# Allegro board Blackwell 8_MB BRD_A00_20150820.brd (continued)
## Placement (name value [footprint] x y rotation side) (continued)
PG4602  GAP-CLOSE-PWR-3-GP  [GAP-CLOSE-PWR-3]  94.6 126.94 90 top
PG4603  GAP-CLOSE-PWR-3-GP  [GAP-CLOSE-PWR-3]  89.65 89.73 0 top
PG4604  GAP-CLOSE-PWR-3-GP  [GAP-CLOSE-PWR-3]  94.6 123.13 270 top
PG4605  GAP-CLOSE-PWR-3-GP  [GAP-CLOSE-PWR-3]  90.03 101.16 90 top
PKEY1  SW-TACT-5P-32-GP  [SKTDLDE010]  101.12 208.5 180 top
PL4601  IND-2D2UH-330-GP  [L6965-1330-UH60]  94.47 116.28 180 top
PL4701  IND-1UH-210-GP  [L2520-D620H48]  99.83 165.3 180 bottom
PL4702  IND-D47UH-78-GP  [L2016-D516H40]  96.18 165.58 180 bottom
PL4703  IND-D47UH-78-GP  [L2016-D516H40]  94.04 165.58 180 bottom
PL4704  IND-D47UH-78-GP  [L2016-D516H40]  91.91 167.25 180 bottom
PL4705  IND-D47UH-78-GP  [L2016-D516H40]  90.36 172.79 90 bottom
PL4706  IND-D47UH-78-GP  [L2016-D516H40]  92.62 179.57 90 bottom
PL4707  IND-D47UH-78-GP  [L2016-D516H40]  94.04 182.04 0 bottom
PL4708  IND-D47UH-78-GP  [L2016-D516H40]  90.54 174.9 90 bottom
PL4801  IND-1UH-210-GP  [L2520-D620H48]  109.31 180.51 270 bottom
PL4802  IND-D47UH-78-GP  [L2016-D516H40]  97.81 184.35 0 bottom
PL4803  IND-D47UH-78-GP  [L2016-D516H40]  105.95 178 270 bottom
PL4804  IND-D47UH-78-GP  [L2016-D516H40]  99.96 184.26 0 bottom
PL4805  IND-D47UH-78-GP  [L2016-D516H40]  102.07 184.26 0 bottom
PL4806  IND-D47UH-78-GP  [L2016-D516H40]  103.64 168.9 270 bottom
PL4807  IND-D47UH-78-GP  [L2016-D516H40]  105.85 173.12 180 bottom
PMIC1  BD2613GW-E2-3-GP  [BGA224J6D2H25]  99.43 175.33 90 bottom
PQ4601  2N7002KDW-GP  [SOT-363H44]  85.84 83.76 180 top
PQ4603  2N7002KDW-GP  [SOT-363H44]  98.41 83.99 180 top
PQ4901  SI2301CDS-T1-GE3-GP  [SOT23DGS2D4H45]  105.47 172.03 0 top
PR4601  22R1J-GP  [R0201H12]  95.49 93.16 180 top
PR4602  22R1J-GP  [R0201H12]  94.98 93.16 180 top
PR4603  10R5J-GP  [R805H24]  91.68 102.81 90 top
PR4605  20R3F-L-GP  [R603H22]  97.9 95.07 180 top
PR4606  1KR2F-3-GP  [R402H16]  98.67 125.04 270 top
PR4608  100KR2F-L1-GP  [R402H16]  91.17 95.07 90 top
PR4610  1KR2F-3-GP  [R402H16]  96.13 93.67 0 top
PR4613  8K2R3J-3-GP  [R603H22]  85.18 86.38 180 top
PR4614  0R2J-2-GP  [R402H16]  90.92 98.62 0 top
PR4615  8K2R3J-3-GP  [R603H22]  86.47 86.38 180 top
PR4617  0R3J-0-U-GP  [R603H22]  94.6 101.8 180 top
PR4618  D01R3721F-GP-U  [R3720H40]  86.8 90.24 180 top
PR4619  10KR2F-2-GP  [R402H16]  88 84.15 90 top
PR4620  100KR2J-1-GP  [R402H16]  88 83.38 90 top
PR4621  100KR2J-1-GP  [R402H16]  91.17 97.35 90 top
PR4622  D01R2512F-3-GP  [R2512H32]  94.6 125.04 180 top
PR4623  12K1R2F-L1-GP  [R402H16]  90.92 93.8 180 top
PR4624  100KR2F-L1-GP  [R402H16]  100.75 81.73 90 top
PR4625  100KR2J-1-GP  [R402H16]  96.89 93.67 0 top
PR4626  499KR2F-1-GP  [R402H16]  102.45 81.73 90 top
PR4627  0R2J-2-GP  [R402H16]  94.35 92.65 180 top
PR4628  100KR2J-1-GP  [R402H16]  96.89 100.53 90 top
PR4629  100KR2J-1-GP  [R402H16]  97.7 99.77 90 top
PR4630  100KR2F-L1-GP  [R402H16]  103.14 83.54 180 top
PR4631  182KR2F-GP  [R402H16]  101.26 84.88 90 top
PR4632  0R2J-2-GP  [R402H16]  93.03 91.97 270 top
PR4633  66K5R2F-GP  [R402H16]  91.68 93.8 180 top
PR4634  100KR2J-1-GP  [R402H16]  88 81.86 270 top
PR4635  0R2J-2-GP  [R402H16]  98.18 88.67 180 top
PR4636  100KR2J-1-GP  [R402H16]  89.78 81.61 90 top
PR4637  100KR2J-1-GP  [R402H16]  88 82.62 270 top
PR4640  10KR1J-GP  [R0201H12]  97.52 88.46 0 top
PR4642  10KR1J-GP  [R0201H12]  97.95 86.84 0 top
PR4643  10KR1J-GP  [R0201H12]  97.42 86.84 0 top
PR4645  10KR1J-GP  [R0201H12]  95.41 88.92 270 top
PR4646  10KR2F-2-GP  [R402H16]  104.02 82.32 180 top
PR4650  100KR2J-1-GP  [R402H16]  99.68 29.15 90 top
PR4901  D01R5F-GP  [R805H24]  106.54 164.41 270 top
PR4902  2R2F-GP  [R402H16]  106.79 160.6 0 top
PR4903  2R2F-GP  [R402H16]  106.79 162.38 180 top
PR4904  2R2F-GP  [R402H16]  107.43 165.81 90 top
PR4905  2R2F-GP  [R402H16]  105.65 165.81 270 top
PR4906  D005R6F-1-GP  [R1206H32]  108.32 161.49 180 top
PR4907  20KR2F-L-GP  [R402H16]  81.85 175.61 270 bottom
PR4908  20KR2F-L-GP  [R402H16]  81.85 176.37 270 bottom
PR4909  20KR2F-L-GP  [R402H16]  81.85 177.13 270 bottom
PR4911  1KR2J-1-GP  [R402H16]  101.59 162.38 0 top
PR4912  10KR2F-2-GP  [R402H16]  100.82 162.38 0 top
PR4913  0R0402-PAD-1-GP  [0R0402-PAD]  107.05 173.81 0 top
PR4914  10KR2F-2-GP  [R402H16]  103.11 162.38 0 top
PR5001  2K2R2F-GP  [R402H16]  100.82 170.25 0 top
PR5002  2K2R2F-GP  [R402H16]  100.06 170.25 0 top
PR5003  100KR2F-L1-GP  [R402H16]  100.06 181.02 0 top
PR5101  10KR2J-3-GP  [R402H16]  102.09 172.28 0 top
PR5102  24K9R2F-L-GP  [R402H16]  101.33 173.93 0 top
PR5103  24K9R2F-L-GP  [R402H16]  100.06 173.43 270 top
PR5104  24K9R2F-L-GP  [R402H16]  100.06 174.44 270 top
PR5105  0R0402-PAD-1-GP  [0R0402-PAD]  98.54 170.76 0 top
PR5106  10KR2J-3-GP  [R402H16]  100.42 95.47 0 bottom
PR5107  0R0402-PAD-1-GP  [0R0402-PAD]  105.9 181.94 90 bottom
PR5108  1KR1J-GP  [R0201H12]  105.65 185.29 90 bottom
PR5109  47KR2F-GP  [R402H16]  104 176.86 0 top
PR5110  0R0402-PAD-1-GP  [0R0402-PAD]  105.52 176.6 0 top
PR5111  0R0402-PAD-1-GP  [0R0402-PAD]  100.06 172.16 0 top
PR5112  0R0402-PAD-1-GP  [0R0402-PAD]  103.49 159.46 90 bottom
PR5113  1MR2F-GP  [R402H16]  100.19 179.14 180 top
PR5114  0R0402-PAD-1-GP  [0R0402-PAD]  105.65 153.87 0 bottom
PR5115  0R0402-PAD-1-GP  [0R0402-PAD]  98.23 177.87 0 top
PR5117  1KR2J-1-GP  [R402H16]  37.32 142.06 180 bottom
PU4601  BQ24770RUYR-3-GP  [QFN28-G2D7H32]  94.47 97.1 90 top
PU4602  SIS407DN-T1-GE3-1-GP  [PPAK-8P-2H45]  99.94 128.09 270 top
PU4603  FDMS3600-02-RJK0215-COLAY-GP  [PPAK-8P-G5324H44-COLAY]  93.84 109.29 270 top
PU4604  SI7121DN-T1-GE3-GP  [PPAK-8P-2H45]  90.03 86.43 270 top
Q501  2N7002W-7-GP  [SOT-323H44]  74.66 179.52 0 bottom
Q1701  PMBS3904-1-GP  [SOT-23-10H44]  89.01 112.85 270 top
Q1702  SI2301CDS-T1-GE3-GP  [SOT23DGS2D4H45]  87.31 28.9 90 bottom
Q1703  SI2301CDS-T1-GE3-GP  [SOT23DGS2D4H45]  91.05 127.58 270 top
Q3001  2N7002W-7-GP  [SOT-323H44]  96.07 68.75 180 top
Q4501  SIS407DN-T1-GE3-1-GP  [PPAK-8P-2H45]  100.57 124.28 0 bottom
R301  182R2F-GP  [R402H16]  69.46 163.77 0 top
R302  182R2F-GP  [R402H16]  69.33 162.38 270 top
R307  10KR1F-GP  [R0201H12]  69.71 178.3 0 bottom
R308  10KR1F-GP  [R0201H12]  69.2 178.3 0 bottom
R309  0R0201-PAD-GP  [0R0201-PAD]  54.98 167.71 180 bottom
R310  0R0201-PAD-GP  [0R0201-PAD]  54.22 180.41 180 bottom
R311  0R0201-PAD-GP  [0R0201-PAD]  53.58 160.98 0 bottom
R312  0R0201-PAD-GP  [0R0201-PAD]  55.1 147.77 180 bottom
R402  402R2F-GP  [R402H16]  82.18 174.32 180 bottom
R403  150R1F-GP  [R0201H12]  78.73 173.43 180 bottom
R404  150R1F-GP  [R0201H12]  78.22 173.43 0 bottom
R406  402R2F-GP  [R402H16]  83.53 172.28 180 bottom
R408  20KR2F-L-GP  [R402H16]  81.39 174.32 180 bottom
R410  10KR2J-3-GP  [R402H16]  78.98 177.74 180 bottom
R411  10KR2J-3-GP  [R402H16]  76.82 179.01 270 bottom
R412  10KR2J-3-GP  [R402H16]  78.6 179.01 90 bottom
R417  10KR2J-3-GP  [R402H16]  76.31 177.74 180 bottom
R418  10KR2J-3-GP  [R402H16]  75.55 177.74 180 bottom
R421  100KR1J-GP  [R0201H12]  89.24 54.38 0 bottom
R422  100KR1J-GP  [R0201H12]  88.99 53.61 90 bottom
R423  100KR1J-GP  [R0201H12]  90 54.02 270 bottom
R501  100R1F-GP  [R0201H12]  83.68 153.23 180 bottom
R502  402R2F-GP  [R402H16]  84.97 159.25 270 bottom
R503  0R2J-2-GP  [R402H16]  67.93 149.42 90 bottom
R504  80D6R1F-GP  [R0201H12]  77.28 158.85 90 top
R507  10KR1J-GP  [R0201H12]  77.2 148.28 270 bottom
R508  10KR1J-GP  [R0201H12]  74.15 152.6 0 bottom
R509  10KR1J-GP  [R0201H12]  70.67 151.07 0 bottom
R510  1KR1J-GP  [R0201H12]  78.35 151.33 180 bottom
R511  100KR1J-GP  [R0201H12]  71.18 151.07 0 bottom
R514  715R2F-GP  [R402H16]  73.77 177.24 90 bottom
R603  90D9R1F-GP  [R0201H11]  84.95 165.78 0 bottom
R604  100KR1J-GP  [R0201H12]  75.68 148.28 90 bottom
R624  2K2R1F-GP  [R0201H12]  70.09 149.42 180 bottom
R625  2K2R1F-GP  [R0201H12]  69.07 149.42 180 bottom
R626  2K2R1F-GP  [R0201H12]  73.01 152.85 270 bottom
R627  2K2R1F-GP  [R0201H12]  69.58 149.42 180 bottom
R628  2K2R1F-GP  [R0201H12]  70.6 149.42 180 bottom
R629  2K2R1F-GP  [R0201H12]  71.11 149.42 180 bottom
R630  2K2R1F-GP  [R0201H12]  73.01 151.33 270 bottom
R631  2K2R1F-GP  [R0201H12]  73.01 152.34 270 bottom
R632  2K2R1F-GP  [R0201H12]  73.01 150.82 270 bottom
R633  2K2R1F-GP  [R0201H12]  73.01 150.31 270 bottom
R634  2K2R1F-GP  [R0201H12]  73.01 151.84 270 bottom
R635  2K2R1F-GP  [R0201H12]  71.61 149.42 180 bottom
R636  2K2R1F-GP  [R0201H12]  73.01 149.8 270 bottom
R637  2K2R1F-GP  [R0201H12]  72.12 149.42 180 bottom
R640  45D3R2F-L-GP  [R402H16]  85.58 165.43 0 bottom
R643  113R2F-GP  [R402H16]  84.97 167.15 180 bottom
R644  100R1F-GP  [R0201H12]  76.69 151.33 0 bottom
R645  2K2R1F-GP  [R0201H12]  84.31 150.44 180 bottom
R647  2K2R1F-GP  [R0201H12]  84.82 150.44 180 bottom
R648  402R2F-GP  [R402H16]  85.58 163.65 0 bottom
R652  0R2J-2-GP  [R402H16]  76.69 149.93 0 bottom
R666  2K2R1F-GP  [R0201H12]  74.03 151.84 90 bottom
R667  2K2R1F-GP  [R0201H12]  74.03 151.33 90 bottom
R703  100KR1J-GP  [R0201H12]  70.22 176.35 0 bottom
R704  100KR1J-GP  [R0201H12]  84.19 153.23 180 bottom
R705  2K2R1F-GP  [R0201H12]  72.12 179.4 270 bottom
R707  10KR1J-GP  [R0201H12]  70.73 176.35 0 bottom
R711  10KR1J-GP  [R0201H12]  72.12 178.13 0 bottom
R713  10KR1J-GP  [R0201H12]  77.2 148.79 90 bottom
R714  100KR1J-GP  [R0201H12]  90.54 163.01 90 bottom
R715  2K49R2F-GP  [R402H16]  80.25 161.62 270 top
R716  200KR1J-GP  [R0201H12]  83.04 161.34 180 bottom
R719  10KR1J-GP  [R0201H12]  80.48 176.52 270 bottom
R720  10KR2J-3-GP  [R402H16]  71.23 177.24 90 bottom
R721  49D9R1F-GP  [R0201H12]  79.84 160.98 270 top
R722  0R2J-2-GP  [R402H16]  81.52 152.34 90 bottom
R723  0R2J-2-GP  [R402H16]  79.34 150.74 0 bottom
R724  2K2R1F-GP  [R0201H12]  72.12 178.89 270 bottom
R728  0R2J-2-GP  [R402H16]  81.14 150.82 0 bottom
R729  2K2R1F-GP  [R0201H12]  71.23 176.35 180 bottom
R730  10MR1J-GP  [R0201H12]  83.68 157.04 0 bottom
R731  10KR1J-GP  [R0201H12]  69.71 176.6 0 bottom
R732  10KR1J-GP  [R0201H12]  82.92 150.44 180 bottom
R733  10KR1J-GP  [R0201H12]  69.46 179.06 270 bottom
R734  10KR2J-3-GP  [R402H16]  77.51 176.14 90 bottom
R735  51R1F-GP  [R0201H12]  73.52 176.35 180 bottom
R736  51R1F-GP  [R0201H12]  72.12 179.9 270 bottom
R737  51R1F-GP  [R0201H12]  73.01 176.35 180 bottom
R738  51R1F-GP  [R0201H12]  72.38 176.35 180 bottom
R739  20KR1J-GP  [R0201H12]  80 159.2 90 top
R740  51R1F-GP  [R0201H12]  73.39 177.87 270 bottom
R741  10KR2J-3-GP  [R402H16]  75.83 176.14 270 bottom
R742  100KR1J-GP  [R0201H12]  74.26 147.34 270 bottom
R748  0R2J-2-GP  [R402H16]  68.57 178.38 0 bottom
R749  100R1F-GP  [R0201H12]  70.22 178.38 180 bottom
R750  0R2J-2-GP  [R402H16]  86.9 76.58 90 bottom
R751  51R1F-GP  [R0201H12]  73.39 178.38 270 bottom
R753  10KR1J-GP  [R0201H12]  71.61 178.13 180 bottom
R754  10KR1J-GP  [R0201H12]  71.74 176.35 180 bottom
R758  10KR1J-GP  [R0201H12]  72.63 178.13 180 bottom
R802  0R0402-PAD-1-GP  [0R0402-PAD]  83.04 163.77 180 bottom
R805  0R2J-2-GP  [R402H16]  80.25 166.06 90 top
R806  0R0402-PAD-1-GP  [0R0402-PAD]  80.25 166.82 270 top
R1305  240R1F-GP  [R0201H12]  48.12 173.43 90 bottom
R1306  240R1F-GP  [R0201H12]  48.12 172.92 90 bottom
R1307  240R1F-GP  [R0201H12]  52.44 180.41 0 bottom
R1308  240R1F-GP  [R0201H12]  51.93 180.41 0 bottom
R1309  40D2R1F-GP  [R0201H12]  54.86 174.42 90 top
R1310  40D2R1F-GP  [R0201H12]  54.72 175.2 0 top
R1311  40D2R1F-GP  [R0201H12]  55.23 175.2 0 top
R1312  40D2R1F-GP  [R0201H12]  56.63 174.06 180 top
R1313  40D2R1F-GP  [R0201H12]  54.09 175.46 180 top
R1314  40D2R1F-GP  [R0201H12]  54.44 173.63 270 top
R1315  40D2R1F-GP  [R0201H12]  53.4 173.22 270 top
R1316  40D2R1F-GP  [R0201H12]  52.87 173.83 270 top
R1317  40D2R1F-GP  [R0201H12]  52.83 174.38 270 top
R1318  40D2R1F-GP  [R0201H12]  52.56 175.03 270 top
R1322  300R1J-GP  [R0201H12]  51.42 174.57 90 top
R1323  300R1J-GP  [R0201H12]  54.22 177.36 180 top
R1324  10KR1J-GP  [R0201H12]  54.98 180.16 90 bottom
R1325  10KR1J-GP  [R0201H12]  54.98 180.67 270 bottom
R1326  10KR1J-GP  [R0201H12]  53.96 167.71 0 bottom
R1327  10KR1J-GP  [R0201H12]  54.47 167.71 180 bottom
R1405  240R1F-GP  [R0201H12]  55.61 147.77 180 bottom
R1406  240R1F-GP  [R0201H12]  56.12 147.77 180 bottom
R1407  240R1F-GP  [R0201H12]  48.12 151.96 90 bottom
R1408  240R1F-GP  [R0201H12]  48.14 151.42 90 bottom
R1409  40D2R1F-GP  [R0201H12]  53.96 154.25 0 top
R1410  40D2R1F-GP  [R0201H12]  52.82 153.87 90 top
R1411  40D2R1F-GP  [R0201H12]  52.82 154.38 90 top
R1412  40D2R1F-GP  [R0201H12]  54.22 153.23 180 top
R1413  40D2R1F-GP  [R0201H12]  53.71 153.23 180 top
R1414  40D2R1F-GP  [R0201H12]  56.22 154.88 270 top
R1415  40D2R1F-GP  [R0201H12]  56.22 154.38 270 top
R1416  40D2R1F-GP  [R0201H12]  55.74 152.73 0 top
R1417  40D2R1F-GP  [R0201H12]  54.72 153.23 180 top
R1418  40D2R1F-GP  [R0201H12]  55.23 153.23 180 top
R1422  300R1J-GP  [R0201H12]  54.22 148.66 90 top
R1423  300R1J-GP  [R0201H12]  51.29 153.87 270 top
R1424  10KR1J-GP  [R0201H12]  54.34 148.03 270 bottom
R1425  10KR1J-GP  [R0201H12]  54.34 147.52 90 bottom
R1426  10KR1J-GP  [R0201H12]  54.34 160.73 90 bottom
R1427  10KR1J-GP  [R0201H12]  54.34 161.23 270 bottom
R1502  0R5J-5-GP  [R805H24]  61.96 149.04 90 bottom
R1601  0R0402-PAD-1-GP  [0R0402-PAD]  103.9 155.62 90 bottom
R1602  0R0402-PAD-1-GP  [0R0402-PAD]  95.36 161.03 90 bottom
R1701  49D9R1F-GP  [R0201H12]  87.92 20.52 270 top
R1702  10KR1J-GP  [R0201H12]  89.9 27.76 0 top
R1705  10KR1J-GP  [R0201H12]  90.44 34.87 270 bottom
R1706  10KR1J-GP  [R0201H12]  90.44 35.38 270 bottom
R1707  10KR1J-GP  [R0201H12]  104.2 39.16 90 top
R1708  100KR1J-GP  [R0201H12]  99.17 31.57 90 top
R1709  10KR1J-GP  [R0201H12]  99.94 26.23 270 top
R1710  10KR1J-GP  [R0201H12]  104.96 39.42 180 top
R1711  1KR1J-GP  [R0201H12]  87.84 49.07 270 top
R1712  1KR1J-GP  [R0201H12]  88.17 47.19 180 top
R1713  100KR1J-GP  [R0201H12]  91.98 27.27 180 top
R1714  1KR1J-GP  [R0201H12]  87.67 47.19 180 top
R1715  1KR1J-GP  [R0201H12]  92.44 24.96 180 top
R1716  10KR1J-GP  [R0201H12]  94.09 40.58 180 top
R1717  10KR1J-GP  [R0201H12]  92.01 35.15 270 bottom
R1718  10KR1J-GP  [R0201H12]  89.01 36.52 0 bottom
R1719  100KR1J-GP  [R0201H12]  89.14 128.19 0 top
R1720  10KR1J-GP  [R0201H12]  86.45 40.61 0 top
R1721  0R0402-PAD-1-GP  [0R0402-PAD]  85.23 29.69 180 bottom
R1722  10KR1J-GP  [R0201H12]  100.32 35.38 0 top
R1723  10KR1J-GP  [R0201H12]  85.46 32.96 270 bottom
R1724  10KR1J-GP  [R0201H12]  85.84 35.63 270 top
R1725  10KR1J-GP  [R0201H12]  89.62 33.75 180 bottom
R1726  10KR1J-GP  [R0201H12]  87.92 19.98 90 top
R1727  10KR1J-GP  [R0201H12]  89.78 23.57 270 top
R1728  10KR1J-GP  [R0201H12]  99.05 38.68 90 top
R1729  10KR1J-GP  [R0201H12]  93.46 40.58 0 top
R1730  100KR1J-GP  [R0201H12]  100.32 37.43 180 top
R1731  0R2J-2-GP  [R402H16]  98.03 40.46 90 top
R1732  100KR1J-GP  [R0201H12]  100.32 36.42 180 top
R1733  10KR1J-GP  [R0201H12]  87.92 16.38 90 top
R1734  10KR1J-GP  [R0201H12]  86.98 40.61 0 top
R1735  10KR1J-GP  [R0201H12]  87.92 19.48 90 top
R1736  100KR1J-GP  [R0201H12]  88.17 46.17 180 top
R1737  0R2J-2-GP  [R402H16]  96.25 40.46 90 top
R1738  1MR2F-GP  [R402H16]  85.58 30.93 270 top
R1739  0R1J-GP  [R0201H12]  100.06 32.2 180 top
R1740  100KR1J-GP  [R0201H12]  87.26 23.36 0 bottom
R1741  100KR1J-GP  [R0201H12]  87.26 24.38 0 bottom
R1742  10KR1J-GP  [R0201H12]  85.08 28.27 180 bottom
R1743  1MR2F-GP  [R402H16]  85.13 29.71 0 top
R1744  10KR1J-GP  [R0201H12]  92.95 40.58 0 top
R1745  100KR1J-GP  [R0201H12]  100.44 34.36 0 top
R1746  1MR2F-GP  [R402H16]  99.22 36.8 90 top
R1747  100KR1J-GP  [R0201H12]  100.44 33.35 0 top
R1748  1MR2F-GP  [R402H16]  101.33 40.46 90 top
R1749  100KR2J-1-GP  [R402H16]  89.52 24.71 180 top
R1750  200KR2J-L1-GP  [R402H16]  90.28 24.71 0 top
R1752  100KR1J-GP  [R0201H12]  87.67 46.17 180 top
R1754  953R2F-GP  [R402H16]  89.27 40.58 270 top
R1757  0R2J-2-GP  [R402H16]  96.76 25.34 270 top
R1758  1KR1J-GP  [R0201H12]  87.87 40.58 90 top
R1759  8K2R2J-3-GP  [R402H16]  92.06 29.54 0 bottom
R1760  1KR1J-GP  [R0201H12]  98.54 29.28 180 top
R1761  100KR1J-GP  [R0201H12]  93.59 27.76 180 top
R1763  10KR1J-GP  [R0201H12]  87.92 18.97 90 top
R1764  10KR1J-GP  [R0201H12]  87.92 18.46 90 top
R1765  10KR1J-GP  [R0201H12]  87.92 17.95 90 top
R1767  10KR1J-GP  [R0201H12]  87.92 16.91 90 top
R1769  100KR1J-GP  [R0201H12]  85.84 38.68 270 top
R1770  10KR1J-GP  [R0201H12]  87.92 17.44 90 top
R1775  10KR1J-GP  [R0201H12]  99.17 32.08 270 top
R1776  10KR1J-GP  [R0201H12]  99.17 32.58 270 top
R1777  10KR1J-GP  [R0201H12]  99.17 33.09 270 top
R1778  10KR1J-GP  [R0201H12]  99.17 34.11 270 top
R1779  10KR1J-GP  [R0201H12]  99.17 33.6 270 top
R1780  10KR1J-GP  [R0201H12]  99.94 34.16 180 top
R1781  10KR1J-GP  [R0201H12]  92.57 27.76 180 top
R1782  10KR1J-GP  [R0201H12]  89.39 27.76 180 top
R1783  10KR1J-GP  [R0201H12]  90.41 27.76 180 top
R1784  10KR1J-GP  [R0201H12]  90.03 31.19 90 bottom
R1785  10KR1J-GP  [R0201H12]  92.82 26.97 90 top
R1786  10KR1J-GP  [R0201H12]  103.95 40.46 180 top
R1787  10KR1J-GP  [R0201H12]  103.41 40.46 0 top
R1788  10KR1J-GP  [R0201H12]  103.41 39.42 0 top
R1789  10KR1J-GP  [R0201H12]  104.2 39.67 270 top
R1801  0R0201-PAD-GP  [0R0201-PAD]  37.4 159.13 0 bottom
R1802  0R0201-PAD-GP  [0R0201-PAD]  38.67 167.25 180 bottom
R1803  3K3R1J-GP  [R0201H12]  37.91 159.13 0 bottom
R1804  10KR1J-GP  [R0201H12]  40.17 159.41 270 bottom
R1805  3K3R1J-GP  [R0201H12]  39.18 167.25 180 bottom
R2001  0R0402-PAD-1-GP  [0R0402-PAD]  104.76 193.11 90 bottom
R2002  100KR1J-GP  [R0201H12]  100.06 204.03 180 bottom
R2005  0R0402-PAD-1-GP  [0R0402-PAD]  96.02 195.96 180 bottom
R2012  22R2F-1-GP  [R402H16]  102.98 205.56 0 bottom
R2013  22R2F-1-GP  [R402H16]  100.19 205.56 0 bottom
R2014  0R0402-PAD-1-GP  [0R0402-PAD]  100.7 203.78 180 bottom
R2015  0R0402-PAD-1-GP  [0R0402-PAD]  96 194.13 0 bottom
R2016  0R0402-PAD-1-GP  [0R0402-PAD]  93.84 194.89 0 bottom
R2017  0R0402-PAD-1-GP  [0R0402-PAD]  89.14 193.62 0 bottom
R2018  0R0201-PAD-GP  [0R0201-PAD]  95.24 196.29 180 bottom
R2019  0R0201-PAD-GP  [0R0201-PAD]  96.76 195.12 180 bottom
R2020  0R0201-PAD-GP  [0R0201-PAD]  104.63 203.98 0 bottom
R2021  0R1J-GP  [R0201H12]  99.05 205.18 270 bottom
R2022  0R0402-PAD-1-GP  [0R0402-PAD]  106.67 194.38 180 bottom
R2023  20KR2J-L2-GP  [R402H16]  99.94 193.62 0 bottom
R2024  0R0402-PAD-1-GP  [0R0402-PAD]  105.78 194.38 180 bottom
R2025  0R0402-PAD-1-GP  [0R0402-PAD]  104.25 194.38 180 bottom
R2026  0R0402-PAD-1-GP  [0R0402-PAD]  105.02 194.38 180 bottom
R2027  0R0402-PAD-1-GP  [0R0402-PAD]  101.71 193.49 0 bottom
R2104  0R0201-PAD-GP  [0R0201-PAD]  111.62 146.88 180 top
R2107  0R0603-PAD-2-GP-U  [0R0603-PAD-1-U]  90.79 22.68 180 bottom
R2108  0R0603-PAD-2-GP-U  [0R0603-PAD-1-U]  89.52 22.68 180 bottom
R2201  2K2R1F-GP  [R0201H12]  97.8 200.78 0 bottom
R2202  2K2R1F-GP  [R0201H12]  95.87 204.03 0 bottom
R2203  0R0201-PAD-GP  [0R0201-PAD]  87.87 195.47 90 bottom
R2204  0R0402-PAD-1-GP  [0R0402-PAD]  87.29 195.42 90 top
R2205  0R0402-PAD-1-GP  [0R0402-PAD]  97.01 206.57 90 bottom
R2206  0R0402-PAD-1-GP  [0R0402-PAD]  105.5 199.13 0 bottom
R2207  0R0201-PAD-GP  [0R0201-PAD]  86.6 195.52 90 bottom
R2208  0R0201-PAD-GP  [0R0201-PAD]  95.87 205.18 0 bottom
R2209  33R2J-2-GP  [R402H16]  94.86 198.95 90 bottom
R2210  33R2J-2-GP  [R402H16]  94.27 203.75 90 bottom
R2211  0R2J-2-GP  [R402H16]  95.24 205.05 180 bottom
R2301  0R0201-PAD-GP  [0R0201-PAD]  107.3 104.59 270 bottom
R2302  0R0201-PAD-GP  [0R0201-PAD]  107.3 103.2 270 bottom
R2303  0R0201-PAD-GP  [0R0201-PAD]  106.41 111.45 270 bottom
R2304  0R0201-PAD-GP  [0R0201-PAD]  106.41 110.05 270 bottom
R2305  0R0201-PAD-GP  [0R0201-PAD]  107.3 105.86 270 bottom
R2306  0R0201-PAD-GP  [0R0201-PAD]  106.41 108.66 270 bottom
R2401  0R0201-PAD-GP  [0R0201-PAD]  113.19 100.15 180 bottom
R2403  0R0201-PAD-GP  [0R0201-PAD]  112.41 93.92 180 bottom
R2501  1KR2J-1-GP  [R402H16]  111.62 196.87 270 top
R2502  0R0201-PAD-GP  [0R0201-PAD]  109.43 193.21 0 top
R2503  0R0201-PAD-GP  [0R0201-PAD]  94.65 189.91 180 top
R2504  100KR1J-GP  [R0201H12]  95.16 189.05 0 top
R2505  0R0201-PAD-GP  [0R0201-PAD]  72.56 183.12 0 bottom
R2506  0R0201-PAD-GP  [0R0201-PAD]  72.05 183.12 0 bottom
R2508  0R0201-PAD-GP  [0R0201-PAD]  107.76 194.41 180 top
R2509  0R0201-PAD-GP  [0R0201-PAD]  66.92 183.84 270 bottom
R2510  0R0201-PAD-GP  [0R0201-PAD]  79.51 187.27 180 bottom
R2511  0R0201-PAD-GP  [0R0201-PAD]  106.79 191.71 180 top
R2512  0R0201-PAD-GP  [0R0201-PAD]  76.47 185.08 0 bottom
R2513  0R0201-PAD-GP  [0R0201-PAD]  107.05 188.41 270 top
R2514  0R0402-PAD-1-GP  [0R0402-PAD]  74.54 186.02 0 bottom
R2515  0R0402-PAD-1-GP  [0R0402-PAD]  89.95 187.55 90 top
R2517  0R1J-GP  [R0201H12]  78.47 187.4 90 bottom
R2518  0R1J-GP  [R0201H12]  73.39 184.14 90 bottom
R2903  15KR2F-GP  [R402H16]  104 19.88 270 top
R2905  93K1R2F-L-GP  [R402H16]  103.87 20.65 270 top
R2908  0R2J-2-GP  [R402H16]  103.87 22.17 270 top
R2909  0R2J-2-GP  [R402H16]  103.87 22.93 270 top
R2910  0R2J-2-GP  [R402H16]  103.87 23.69 270 top
R2911  0R2J-2-GP  [R402H16]  103.62 26.23 270 top
R2912  3K3R1J-GP  [R0201H12]  109.33 28.27 180 top
R2913  3K3R1J-GP  [R0201H12]  106.41 35.38 90 top
R2914  3K3R1J-GP  [R0201H12]  107.45 36.67 180 top
R2915  3K3R1J-GP  [R0201H12]  107.96 36.67 180 top
R2916  0R2J-2-GP  [R402H16]  107.63 25.65 180 top
R2917  0R2J-2-GP  [R402H16]  106.87 25.65 180 top
R2918  1KR2J-1-GP  [R402H16]  104.89 46.07 90 top
R2919  0R0402-PAD-1-GP  [0R0402-PAD]  101.74 18.23 180 top
R2920  0R0402-PAD-1-GP  [0R0402-PAD]  102.53 18.23 180 top
R2921  0R2J-2-GP  [R402H16]  95.41 22.52 270 top
R2922  0R2J-2-GP  [R402H16]  96.94 64.18 180 top
R2923  0R0402-PAD-1-GP  [0R0402-PAD]  103.62 142.57 180 top
R2924  0R0402-PAD-1-GP  [0R0402-PAD]  99.02 25.5 90 top
R2925  0R2J-2-GP  [R402H16]  99.05 24.58 270 top
R3001  100KR1J-GP  [R0201H12]  97.7 70.18 0 top
R3002  1MR2F-GP  [R402H16]  97.73 68.8 0 top
R3016  4K7R1J-GP  [R0201H12]  98.08 73.32 90 top
R3017  4K7R1J-GP  [R0201H12]  98.08 72.82 270 top
R3019  0R0402-PAD-1-GP  [0R0402-PAD]  97.42 66.34 90 top
R3020  0R2J-2-GP  [R402H16]  97.42 67.2 90 top
R3021  100KR1J-GP  [R0201H12]  107.78 70.1 270 top
R3022  100KR1J-GP  [R0201H12]  107.78 69.59 270 top
R3026  10KR1J-GP  [R0201H12]  98.67 67.94 180 top
R3101  0R0402-PAD-1-GP  [0R0402-PAD]  97.73 64.18 0 top
R3125  0R0201-PAD-GP  [0R0201-PAD]  102.4 59.05 0 top
R3126  0R0201-PAD-GP  [0R0201-PAD]  102.91 59.05 0 top
R3127  0R0201-PAD-GP  [0R0201-PAD]  103.41 59.05 0 top
R3128  0R0201-PAD-GP  [0R0201-PAD]  103.92 59.05 0 top
R3129  0R0201-PAD-GP  [0R0201-PAD]  101.21 86.81 270 bottom
R3130  0R0201-PAD-GP  [0R0201-PAD]  104.43 59.05 180 top
R3131  0R0201-PAD-GP  [0R0201-PAD]  101.89 59.05 180 top
R3146  0R0402-PAD-1-GP  [0R0402-PAD]  107.94 87.57 90 bottom
R3161  4K7R1J-GP  [R0201H12]  100.95 83.51 0 bottom
R3162  0R1J-GP  [R0201H12]  101.46 83.51 180 bottom
R3163  4K7R1J-GP  [R0201H12]  108.19 83.64 90 bottom
R3164  0R1J-GP  [R0201H12]  107.43 83.38 180 bottom
R3165  0R0201-PAD-GP  [0R0201-PAD]  101.21 86.3 270 bottom
R3166  0R1J-GP  [R0201H12]  101.46 85.54 180 bottom
R3167  4K7R1J-GP  [R0201H12]  100.95 85.54 0 bottom
R3168  4K7R1J-GP  [R0201H12]  108.19 85.16 90 bottom
R3169  0R1J-GP  [R0201H12]  107.43 85.42 0 bottom
R3170  4K7R1J-GP  [R0201H12]  108.19 84.65 90 bottom
R3171  4K7R1J-GP  [R0201H12]  100.95 84.53 0 bottom
R3172  0R1J-GP  [R0201H12]  101.46 84.53 180 bottom
R3173  0R1J-GP  [R0201H12]  107.43 84.4 180 bottom
R3401  100KR1J-GP  [R0201H12]  94.45 57.07 0 top
R3402  100KR1J-GP  [R0201H12]  93.15 58.87 270 top
R3403  100KR2J-1-GP  [R402H16]  88.86 49.32 0 top
R3404  100KR1J-GP  [R0201H12]  85.58 54.86 180 bottom
R3405  0R2J-2-GP  [R402H16]  92.14 37.16 90 bottom
R3407  1KR2J-1-GP  [R402H16]  88.4 51.05 180 top
R3408  1KR2J-1-GP  [R402H16]  87.64 51.05 180 top
R3807  10KR1J-GP  [R0201H12]  112.6 133.9 0 top
R3902  0R0402-PAD-1-GP  [0R0402-PAD]  98.03 77.16 180 top
R3904  0R0402-PAD-1-GP  [0R0402-PAD]  91.93 75.89 90 bottom
R3905  0R2J-2-GP  [R402H16]  94.22 78.3 270 top
R4003  100KR1J-GP  [R0201H12]  9.38 141.8 180 bottom
R4004  0R1J-GP  [R0201H12]  14.34 141.55 180 bottom
R4005  10KR1J-GP  [R0201H12]  13.32 140.53 0 bottom
R4006  0R1J-GP  [R0201H12]  18.02 141.55 180 bottom
R4007  0R1J-GP  [R0201H12]  18.53 141.55 180 bottom
R4008  0R1J-GP  [R0201H12]  13.32 141.55 0 bottom
R4009  0R1J-GP  [R0201H12]  17.51 141.55 180 bottom
R4010  0R1J-GP  [R0201H12]  69.1 176.55 180 bottom
R4012  0R1J-GP  [R0201H12]  23.86 141.68 180 bottom
R4013  0R1J-GP  [R0201H12]  21.07 142.06 0 bottom
R4014  0R1J-GP  [R0201H12]  20.56 142.06 0 bottom
R4017  100KR2J-1-GP  [R402H16]  11.92 141.55 90 bottom
R4018  10KR1J-GP  [R0201H12]  9.89 141.8 180 bottom
R4020  100KR2J-1-GP  [R402H16]  11.04 142.31 90 bottom
R4021  0R1J-GP  [R0201H12]  13.83 141.55 180 bottom
R4101  10KR1J-GP  [R0201H12]  82.74 184.2 0 bottom
R4102  0R0402-PAD-1-GP  [0R0402-PAD]  86.09 187.02 180 bottom
R4103  0R0201-PAD-GP  [0R0201-PAD]  80.38 186.61 90 bottom
R4104  1KR2J-1-GP  [R402H16]  84.64 183.97 0 bottom
R4105  0R0402-PAD-1-GP  [0R0402-PAD]  84.82 189.53 180 bottom
R4106  10KR1J-GP  [R0201H12]  80.5 185.14 0 bottom
R4107  0R0201-PAD-GP  [0R0201-PAD]  80.38 187.12 90 bottom
R4108  0R0201-PAD-GP  [0R0201-PAD]  82.23 184.2 0 bottom
R4109  0R0201-PAD-GP  [0R0201-PAD]  81.72 184.2 180 bottom
R4110  0R0201-PAD-GP  [0R0201-PAD]  81.22 184.2 180 bottom
R4201  0R0402-PAD-1-GP  [0R0402-PAD]  41.46 176.73 270 top
R4202  0R0402-PAD-1-GP  [0R0402-PAD]  42.15 174.59 270 top
R4203  0R0402-PAD-1-GP  [0R0402-PAD]  35.93 177.74 180 top
R4204  0R0402-PAD-1-GP  [0R0402-PAD]  39.74 177.87 180 top
R4205  0R0402-PAD-1-GP  [0R0402-PAD]  113.23 134.28 180 top
R4207  0R0402-PAD-1-GP  [0R0402-PAD]  38.44 176.02 0 top
R4208  0R0402-PAD-1-GP  [0R0402-PAD]  39.2 175.53 0 top
R4209  10KR1J-GP  [R0201H12]  40.04 176.14 180 top
R4301  0R0402-PAD-1-GP  [0R0402-PAD]  94.98 73.86 180 top
R4302  0R2J-2-GP  [R402H16]  94.09 73.86 180 top
R4303  1KR1J-GP  [R0201H12]  87.84 49.58 90 top
R4310  100KR1J-GP  [R0201H12]  87.74 74.49 180 bottom
R4311  100KR1J-GP  [R0201H12]  93.84 75.76 180 bottom
R4401  63K4R2F-2-GP  [R402H16]  101.18 49.25 270 top
R4402  30KR2F-GP  [R402H16]  103.19 49.75 270 top
R4403  100KR1J-GP  [R0201H12]  102.83 55.27 270 top
R4404  2KR2J-1-GP  [R402H16]  107.81 52.52 90 top
R4405  2KR2J-1-GP  [R402H16]  95.87 59.63 270 top
R4501  200KR2J-L1-GP  [R402H16]  101.46 127.58 270 bottom
R4502  100R2J-2-GP  [R402H14]  88.12 129.99 90 top
R4503  100R2J-2-GP  [R402H14]  88.12 130.75 90 top
R4504  100R2J-2-GP  [R402H14]  88.12 133.42 90 top
R4801  0R3J-6-GP  [R603H22]  108.8 183.81 0 bottom
R4902  300R1J-GP  [R0201H12]  100.85 16.02 270 bottom
R4903  1KR1J-GP  [R0201H12]  100.85 15.46 270 bottom
R5211  10KR2J-3-GP  [R402H16]  91.68 143.2 180 top
R5212  255KR1F-GP  [R0201H12]  92.7 143.45 90 top
R5213  300KR1F-GP  [R0201H12]  92.7 142.95 90 top
R5214  0R0201-PAD-GP  [0R0201-PAD]  91.3 144.72 270 top
R5215  100KR1F-GP  [R0201H12]  93.46 143.2 0 top
R5216  1KR1F-GP  [R0201H12]  93.97 142.18 0 top
R5217  0R2J-2-GP  [R402H16]  89.14 143.58 0 top
R5218  91KR1F-GP  [R0201H11]  94.22 142.95 90 top
R5219  28KR1F-GP  [R0201H12]  94.22 143.45 270 top
R5401  10KR1J-GP  [R0201H12]  113.14 196.26 90 top
R5403  100R1J-GP  [R0201H12]  105.52 195.91 180 top
R5404  100R1J-GP  [R0201H12]  114.03 178 270 top
R5405  100R1J-GP  [R0201H12]  113.27 150.08 180 top
R5406  100R1J-GP  [R0201H12]  111.77 192.35 0 top
R5409  10KR1J-GP  [R0201H12]  101.84 130.5 90 bottom
R5410  100KR2J-1-GP  [R402H16]  103.24 130.5 90 bottom
R5412  100R1J-GP  [R0201H12]  102.98 131.9 90 top
R5601  0R0402-PAD-1-GP  [0R0402-PAD]  63.87 142.95 270 bottom
R5602  0R0402-PAD-1-GP  [0R0402-PAD]  63.87 143.71 270 bottom
R5603  0R2J-2-GP  [R402H16]  48.12 140.28 90 bottom
R5704  0R0402-PAD-1-GP  [0R0402-PAD]  42.02 154.12 0 bottom
R5705  0R2J-2-GP  [R402H16]  41.95 156.38 0 bottom
R5706  0R0402-PAD-1-GP  [0R0402-PAD]  40.5 158.44 90 bottom
R5707  0R0402-PAD-1-GP  [0R0402-PAD]  39.61 157.55 270 bottom
R5712  0R0402-PAD-1-GP  [0R0402-PAD]  39.23 149.17 0 bottom
R5717  100KR1J-GP  [R0201H12]  41.52 150.06 90 bottom
R5720  100KR1J-GP  [R0201H12]  40.5 150.06 90 bottom
R5721  294KR2F-1-GP  [R402H16]  104.02 84.09 180 top
R5722  340KR2F-L-GP  [R402H16]  105.68 84.6 90 top
R5723  1KR1J-GP  [R0201H12]  98.16 85.92 270 top
R5724  1KR1J-GP  [R0201H12]  96.63 83.76 0 top
R5725  100KR1J-GP  [R0201H12]  42.02 146.76 90 bottom
R5726  100KR1J-GP  [R0201H12]  41.01 146.76 90 bottom
RAM1  H9CCNNNBKTMLBR-NTD-GP  [BGA253G110115H38]  54.72 174.06 270 bottom
RAM2  H9CCNNNBKTMLBR-NTD-GP  [BGA253G110115H38]  54.47 154.38 0 bottom
RT5101  NTC-47K-6-GP-U  [NTC-402H22-U]  92.06 161.49 0 bottom
RT5102  NTC-47K-6-GP-U  [NTC-402H22-U]  104.23 55.27 90 top
RT5103  NTC-47K-6-GP-U  [NTC-402H22-U]  51.57 164.21 0 bottom
RTC1  ACES-CON2-15-GP-U1  [50281-0020N-001]  33.02 137.76 180 bottom
SH1  MB_EMI_SHIELDING_FRAME_ SOC_T4  [SKT1603X1424-24]  66.72 164.07 180 bottom
SH2  SKT951X1419-24-S-GP  [SKT951X1419-24-S]  97.6 62.27 0 top
SH4  SKT520X1447-24-GP  [SKT520X1447-24]  104.92 98.07 180 bottom
SH5  SKT560X460-24-GP  [SKT560X460-24]  102.34 15.49 180 bottom
SPK1  ACES-CON2-15-GP-U1  [50281-0020N-001]  87.02 16.94 90 bottom
SPR1  SPRING-171-GP  [SPR5128H111]  82.52 191.1 270 bottom
SPR2  SPRING-171-GP  [SPR5128H111]  55.02 165.1 180 top
SPR3  SPRING-171-GP  [SPR5128H111]  80.02 139.1 270 top
SPR4  SPRING-123-GP  [SPR4013-1H75]  93.05 16.07 90 top
TP1  ACES-CON10-57-GP  [51651-01001-001]  94.02 71.55 180 bottom
TP401  TPAD14-OP-GP  [TPAD14-OP]  77.99 174.67 180 bottom
TP601  TPAD14-OP-GP  [TPAD14-OP]  83.55 149.4 180 bottom
TP701  TPAD14-OP-GP  [TPAD14-OP]  89.5 153.06 180 bottom
TP702  TPAD14-OP-GP  [TPAD14-OP]  76.62 152.52 180 bottom
TP801  TPAD14-OP-GP  [TPAD14-OP]  71.89 152.39 180 bottom
TP802  TPAD14-OP-GP  [TPAD14-OP]  70.95 163.7 0 top
TP803  TPAD14-OP-GP  [TPAD14-OP]  80.2 173.93 180 bottom
TP804  TPAD14-OP-GP  [TPAD14-OP]  76.19 163.52 0 top
TP805  TPAD14-OP-GP  [TPAD14-OP]  70.98 179.24 180 bottom
TP1601  TPAD14-OP-GP  [TPAD14-OP]  78.09 149.83 90 bottom
TP1602  TPAD14-OP-GP  [TPAD14-OP]  69.53 151.02 90 bottom
TP1707  TPAD14-OP-GP  [TPAD14-OP]  99.17 39.57 90 top
TP1711  TPAD14-OP-GP  [TPAD14-OP]  85.38 40.63 90 top
TP1712  TPAD14-OP-GP  [TPAD14-OP]  99.3 37.79 90 top
TP1713  TPAD14-OP-GP  [TPAD14-OP]  96.51 26.49 90 top
TP1715  TPAD14-OP-GP  [TPAD14-OP]  99.05 30.42 90 top
TP1717  TPAD14-OP-GP  [TPAD14-OP]  95.74 27.63 90 top
TP1719  TPAD14-OP-GP  [TPAD14-OP]  84.95 33.22 90 top
TP1720  TPAD14-OP-GP  [TPAD14-OP]  103.59 37.79 270 top
TP2001  TPAD14-OP-GP  [TPAD14-OP]  97.29 197.07 180 bottom
TP2401  TPAD14-OP-GP  [TPAD14-OP]  108.11 94.31 180 bottom
TP2905  TPAD14-OP-GP  [TPAD14-OP]  107.17 15.84 0 top
TP2906  TPAD14-OP-GP  [TPAD14-OP]  107.17 17.22 0 top
TP2907  TPAD14-OP-GP  [TPAD14-OP]  102.58 19.73 0 top
TP2908  TPAD14-OP-GP  [TPAD14-OP]  104.51 17.09 0 top
TP2909  TPAD14-OP-GP  [TPAD14-OP]  102.35 21.92 0 top
TP2910  TPAD14-OP-GP  [TPAD14-OP]  101.92 20.77 0 top
TP2912  TPAD14-OP-GP  [TPAD14-OP]  114.41 20.65 0 top
TP2913  TPAD14-OP-GP  [TPAD14-OP]  112.91 20.16 0 top
TP2916  TPAD14-OP-GP  [TPAD14-OP]  114.29 22.04 0 top
TP2918  TPAD14-OP-GP  [TPAD14-OP]  113.02 22.55 0 top
TP2919  TPAD14-OP-GP  [TPAD14-OP]  113.27 21.36 0 top
TP3001  TPAD14-OP-GP  [TPAD14-OP]  106.79 77.52 0 top
TP3002  TPAD14-OP-GP  [TPAD14-OP]  104.99 77.64 0 top
TP3003  TPAD14-OP-GP  [TPAD14-OP]  96.28 71.72 0 top
TP3005  TPAD14-OP-GP  [TPAD14-OP]  96.94 72.94 0 top
TP3006  TPAD14-OP-GP  [TPAD14-OP]  97.62 71.75 0 top
TP3901  TPAD14-OP-GP  [TPAD14-OP]  93.97 77.41 180 bottom
TP3902  TPAD14-OP-GP  [TPAD14-OP]  90.79 77.52 180 bottom
TP3903  TPAD14-OP-GP  [TPAD14-OP]  93.03 77.31 0 top
TP4002  TPAD14-OP-GP  [TPAD14-OP]  19.54 141.42 180 bottom
TP4101  TPAD14-OP-GP  [TPAD14-OP]  80.38 188.29 180 bottom
TP4501  TPAD14-OP-GP  [TPAD14-OP]  97.4 127.96 180 bottom
TP4502  TPAD14-OP-GP  [TPAD14-OP]  98.67 127.96 180 bottom
TP4503  TPAD14-OP-GP  [TPAD14-OP]  99.94 127.96 180 bottom
TP4504  TPAD14-OP-GP  [TPAD14-OP]  97.9 131.14 180 bottom
TP4505  TPAD14-OP-GP  [TPAD14-OP]  98.54 132.28 180 bottom
TP4506  TPAD14-OP-GP  [TPAD14-OP]  97.27 132.28 180 bottom
TP5101  TPAD14-OP-GP  [TPAD14-OP]  105.78 169.69 180 bottom
TP5102  TPAD14-OP-GP  [TPAD14-OP]  104.61 170.61 180 bottom
TP5103  TPAD14-OP-GP  [TPAD14-OP]  104.43 181.43 180 bottom
TP5104  TPAD14-OP-GP  [TPAD14-OP]  105.6 175.13 270 top
TP5105  TPAD14-OP-GP  [TPAD14-OP]  103.52 180.59 180 bottom
TP5106  TPAD14-OP-GP  [TPAD14-OP]  106.92 186.71 180 bottom
TP5107  TPAD14-OP-GP  [TPAD14-OP]  103.49 182.37 180 bottom
TP5108  TPAD14-OP-GP  [TPAD14-OP]  89.83 186.61 180 bottom
TP5109  TPAD14-OP-GP  [TPAD14-OP]  91.05 186.41 180 bottom
TP5110  TPAD14-OP-GP  [TPAD14-OP]  89.78 185.36 180 bottom
TP5111  TPAD14-OP-GP  [TPAD14-OP]  92.26 186.43 180 bottom
TP5112  TPAD14-OP-GP  [TPAD14-OP]  105.68 168.45 180 bottom
TP5113  TPAD14-OP-GP  [TPAD14-OP]  90.23 167.25 180 bottom
TP5401  TPAD14-OP-GP  [TPAD14-OP]  105.27 197.05 0 top
TP5402  TPAD14-OP-GP  [TPAD14-OP]  112.89 178 0 top
TP5403  TPAD14-OP-GP  [TPAD14-OP]  112.86 151.48 0 top
TP5404  TPAD14-OP-GP  [TPAD14-OP]  111.62 191.08 0 top
TP5405  TPAD14-OP-GP  [TPAD14-OP]  105.27 194.76 0 top
TP5601  TPAD14-OP-GP  [TPAD14-OP]  52.82 144.47 180 bottom
TP5602  TPAD14-OP-GP  [TPAD14-OP]  54.06 144.47 180 bottom
U701  UM6K1N-GP  [SC70-6H44]  86.22 74.75 180 bottom
U1702  NTS0102GF-GP  [XSON8-1410H20]  88.68 67.48 270 bottom
U1703  TLV70533YFPR-GP  [CSP4J076H20]  85.46 31.57 90 bottom
U1704  MEC1633X-AUE-GP  [BGA169D1111H56]  92.44 34.23 90 top
U1705  TLV70533YFPR-GP  [CSP4J076H20]  96.58 88.46 0 top
U1706  UM6K1N-GP  [SC70-6H44]  90.66 130.63 90 top
U1707  NTS0102GF-GP  [XSON8-1410H20]  85.97 34.74 0 bottom
U1708  UM6K1N-GP  [SC70-6H44]  101.84 36.52 180 top
U1709  UM6K1N-GP  [SC70-6H44]  85.74 23.49 0 bottom
U1710  UM6K1N-GP  [SC70-6H44]  101.97 33.47 0 top
U2001  ALC5672-VB-CGT-GP  [QFN48J6-G465H40]  101.71 198.7 270 bottom
U2501  UM6K1N-GP  [SC70-6H44]  109.33 196.01 270 top
U2901  PTPS65982AAZQZR-GP-U  [BGA96G60-1H40]  108.83 21.15 0 top
U2903  W25Q16DVZPIQ-GP  [DFN8A5060-G435345H32]  106.3 31.48 0 top
U3101  HD3SS460RHRR-1-GP  [QFN28-G4121H32]  103.19 61.89 180 top
U3102  SN75DP130SSRGZR-GP  [QFN48-G5D8H40]  102.96 71.37 90 top
U3401  SIP32402ADNP-T1GE4-GP  [DFN4G1216-GD91D55H24]  90.46 50.31 270 top
U3402  UM6K1N-GP  [SC70-6H44]  92.87 57.14 0 top
U3403  SIP32402ADNP-T1GE4-GP  [DFN4G1216-GD91D55H24]  87.77 55.19 270 bottom
U4002  UM6K1N-GP  [SC70-6H44]  11.54 139.9 90 bottom
U4101  SX9500IULTRT-GP  [QFN20-G1D75H24]  82.92 186.74 180 bottom
U4301  NTS0102GF-GP  [XSON8-1410H20]  87.13 71.95 0 bottom
U4302  UM6K1N-GP  [SC70-6H44]  89.01 76.14 0 bottom
U4401  LP8556SQ-E09-NOPB-GP  [QFN24G4-G2D8H32]  100.74 52.62 270 top
U4501  UM6K1N-GP  [SC70-6H44]  103.62 128.6 0 bottom
U4602  74LVC1G74DP-GP  [SSOIC8H44]  94.78 86.13 270 top
U4603  OPA348AIDCKR-GP  [SC70-5H44]  101.26 83.31 270 top
U4901  UM6K1N-GP  [SC70-6H44]  99.4 17.32 90 bottom
U5101  TLV70533YFPR-GP  [CSP4J076H20]  105.65 155.77 270 bottom
U5202  SY7066QMC-GP  [QFN10G2020-1H32]  93.59 145.61 270 top
U5401  G601A31U-GP  [DFN6G1D5H32]  101.08 131.39 90 top
U5407  HPA02232ARGER-GP  [QFN24-G2D25H40]  104.51 84.86 270 bottom
U5702  NPCT650JAAYX-GP  [QFN32G5-G3D6H32]  38.47 153.74 180 bottom
U5706  UM6K1N-GP  [SC70-6H44]  41.26 148.53 90 bottom
U5707  AZ1043-04F-R7G-GP  [DFN10G2510H22]  98.26 11.88 180 bottom
U5708  AZ1043-04F-R7G-GP  [DFN10G2510H22]  104.61 11.86 180 bottom
U5709  UM6K1N-GP  [SC70-6H44]  41.74 145.18 90 bottom
VDKEY1  SW-TACT-3P-5-GP-U  [SKRTLAE010-U]  114.87 155.59 90 top
VUKEY1  SW-TACT-3P-5-GP-U  [SKRTLAE010-U]  114.87 172.91 90 top
WC3701  SC1U6D3V2KX-GP  [C402H22]  102.73 28.65 180 top
WC3702  SC4D7U6D3V2MX-GP-U  [C402-TO0D2H26]  101.84 28.65 180 top
WC3703  SC1U6D3V2KX-GP  [C402H22]  101.33 26.11 270 top
WC3704  SC1U6D3V2KX-GP  [C402H22]  100.95 28.65 180 top
WC3705  SC1U6D3V2KX-GP  [C402H22]  100.44 30.81 180 top
WC3706  0R1J-GP  [R0201H12]  111.03 37.54 0 top
WC3707  0R1J-GP  [R0201H12]  112.05 37.54 180 top
WC3708  SC2D2P25V1BN-RL-GP  [C0201H13]  115.55 35.13 180 top
WC3709  0R1J-GP  [R0201H12]  112.45 35.13 0 top
WC3710  SC3D3P50V1CN-GP  [C0201H13]  116.06 27.94 0 top
WC3713  SCD1U10V1KX-GP  [C0201H13]  102.96 41.42 180 bottom
WC3714  SCD1U10V1KX-GP  [C0201H13]  103.47 41.42 180 bottom
WC3715  SCD1U10V1KX-GP  [C0201H13]  108.95 27 0 top
WC3716  SCD1U10V1KX-GP  [C0201H13]  109.46 27 0 top
WC3717  SCD1U10V1KX-GP  [C0201H13]  99.17 26.87 0 top
WC3718  SCD1U10V1KX-GP  [C0201H13]  98.67 26.87 0 top
WL3701  0R1J-GP  [R0201H12]  111.54 37.54 0 top
WR3703  10KR1J-GP  [R0201H12]  98.89 41.22 90 bottom
WR3704  0R0201-PAD-GP  [0R0201-PAD]  97.55 41.47 180 bottom
WR3705  10KR1J-GP  [R0201H12]  100.65 41.7 270 bottom
WR3706  0R0402-PAD-1-GP  [0R0402-PAD]  101.33 30.81 180 top
WR3707  0R0402-PAD-1-GP  [0R0402-PAD]  101.33 26.87 90 top
WR3708  10KR1J-GP  [R0201H12]  98.89 41.73 90 bottom
WR3710  0R0201-PAD-GP  [0R0201-PAD]  98.13 41.47 0 bottom
WR3711  0R0201-PAD-GP  [0R0201-PAD]  100.09 41.19 270 bottom
WR3712  0R0201-PAD-GP  [0R0201-PAD]  102.07 41.42 0 bottom
WR3713  0R0201-PAD-GP  [0R0201-PAD]  101.56 41.42 0 bottom
WU3701  WLAN-MODULE-96-GP  [LGA100G1612-G8PH75]  102.83 32.46 270 bottom
X701  XTAL-19D2MHZ-24-GP  [S-OSC4-2520-3H40]  84.57 161.23 270 bottom
X703  XTAL-32D768KHZ-91-GP  [SMD49-3215-0713H36]  84.95 156.79 0 bottom
X1701  XTAL-32D768KHZ-91-GP  [SMD49-3215-0713H36]  87.11 26.49 270 top
XDP1  PSC-CONN40A-GP  [AXT340124]  55.33 141.55 180 bottom

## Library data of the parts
ANT1 = 20449-001E: tolerance: 20.G0019.001
ANT2 = AA077: tolerance: 069.E0004.0001
AUDIO1 = 2SJ3108-028111F: tolerance: 022.10002.0851
BATT1 = 51483-00801-001: tolerance: 020.F0256.0008
BIOS1 = DFN8A5060-G435345H32: tolerance: 072.25128.0F01
BSKT1 = SKT-SOIC8-2-UH121: tolerance: 62.10089.131
C501 C1314 C1403 C1803 C3903 C3905 C4001 C4007 C4302 C4304 C4308 C4309 = C0201H13: tolerance: 78.10420.50L
C701 C702 = C0201H13: tolerance: 78.15032.1SL
C706 C1190 C1191 C1601 C1603 C1702 C1704 C1708 C1709 C1714 C1717 C1718 C1720 C1721 C1723 C1726-C1732 C2004 C2005 C2012 C2015 C2016 C2019 C2101 C2302 C2401 C2403 C3009 C3010 C3031 C3140-C3143 C4202 C4203 C4206 C4208 C4210 C5406 C5703-C5707 WC3713-WC3718 = C0201H13: tolerance: 78.10423.5SL
C707 C708 = C0201H13: tolerance: 78.18032.1SL
C709 C2402 = C0201H14: tolerance: 78.10510.5SL
C710-C712 C1802 = C402H22: tolerance: 78.10034.1FL
C1101-C1104 C1107-C1110 C1113-C1153 C1156-C1187 C1192-C1204 C1313 C1404 C1501-C1517 C1519 C1520 C1523 C1525 C1526 C1531-C1534 C1539-C1542 C1547 C1553 = C0201H13: tolerance: 78.4741T.5SL
C1105 C1106 C1111 C1112 C1154 C1155 C1188 C1189 C1312 C1402 C1606 C2102 WC3701 WC3703-WC3705 = C402H22: tolerance: 78.10520.5FL
C1405 = C402H22: tolerance: 078.56034.01FS
C1406 = C402H22: tolerance: 78.68034.1FLLL
C1407-C1409 = C402H22: tolerance: 78.47034.1FL
C1602 C1605 C1712 C2003 C2006 C2007 C2010 C2011 C2017 C2507 C2515-C2517 C2913 C5710 PC4903 PC4904 WC3702 = C402-TO0D2H26: tolerance: 78.47510.5FL
C1701 C1705 C1706 C1713 C1722 C5711 C5712 PC4905-PC4909 PC4912 PC4916-PC4919 PC5004 PC5101-PC5104 = C402H22: tolerance: 78.10521.5FL
C1703 = C402H22: tolerance: 78.47224.2FL
C1710 C1711 C5402-C5405 = C0201H13: tolerance: 78.33032.1SL
C1715 C5219 = C402H22: tolerance: 78.22224.2FL
C1716 C4102 C4104 = C0201H13: tolerance: 78.10122.20L
C1719 C2013 C2022 C3032 C3401 C3403 C3407 C3408 C4201 C4207 PC4913 PC4914 = C402-TO0D2H28: tolerance: 78.10610.5FL
C2001 C2002 C2008 C2009 C2014 C2018 C2020 = C402H22: tolerance: 78.22520.5FL
C2021 C2905 C3132 C3405 C3406 C4404 C4405 PC5001 PC5003 = C0201H13: tolerance: 78.10421.5SL
C2103 C2104 = C0201H13: tolerance: 78.68122.2SL
C2201-C2203 C4009 C4010 = C402H22: tolerance: 78.22044.1FL
C2204 C2205 C3102-C3108 C3127 = C0201H13: tolerance: 078.10320.02SD
C2301 = C603H36: tolerance: 78.47520.5BL
C2404 = C402H22: tolerance: 78.33034.1FL
C2501 C2504 C2508 C2511 C2514 C2520 C2521 = C402H22: tolerance: 78.10423.2FL
C2502 C2503 C2509 C2510 C2512 C2518 C2519 C2915 C4301 = C603H38: tolerance: 78.10610.5BL
C2505 C2506 C2513 = C0201H13: tolerance: 78.22032.1SL
C2902 C5401 = C402H22: tolerance: 78.22420.5FL
C2903 C2904 C5215 C5218 C5227 PC4701-PC4713 PC4715 PC4716 PC4723-PC4730 PC4732 PC4801-PC4810 PC4818-PC4830 PC4832-PC4834 PC4836 PC4837 PC4839-PC4842 PC4901 PC4902 PC4910 PC4915 = C603H40: tolerance: 78.22610.5BL
C2906 PC4607 PC4623 = C603H32: tolerance: 78.10524.5BL
C2907-C2910 C3033 C3133 C4209 PC4602 PC4617 = C402H22: tolerance: 78.10324.2FL
C2911 C2912 C5228 = C0201H13: tolerance: 78.22122.2SL
C2914 C2916-C2918 C3024 C3902 C3904 C4101 C4103 C5223 C5224 PC4628 = C402H22: tolerance: 78.10523.5FL
C3001-C3008 C3011-C3018 C3138 C3139 C3144-C3149 = C0201H13: tolerance: 78.10423.5SL; signal model: 2pins
C3025 = C402H22: tolerance: 78.22523.5FL
C3402 C3404 C3409 C3410 = C0201H13: tolerance: 78.10320.2SL
C3901 C4002 C4006 C4401 C4402 PC4503 PC4603 PC4605 PC4606 PC4610 PC4611 PC4622 PC4629 PC4630 PC4717-PC4720 PC4722 PC4811 PC4812 PC4831 = C603H36: tolerance: 78.10613.5BL
C4008 = C603H38: tolerance: 78.22522.5BL
C4303 = C402H22: tolerance: 78.22510.5FL
C4305 C4306 C5713 C5714 = C402H22: tolerance: 78.10232.2FL
C4403 C4406 PC4604 PC4608 PC4614 PC4618 PC4619 PC4625 = C603H40: tolerance: 78.10612.5BL
C5216 C5217 C5220-C5222 C5225 C5226 PC4813 PC4815 PC4817 = C603H42: tolerance: 078.22613.05B1
C5709 = C402H22: tolerance: 78.22423.5FL
CABLE1-CABLE3 = SPR260243H68: tolerance: 34.4EO01.001
CAMF1 = FH35C-21S-0D3SHW-50: tolerance: 20.K0739.021
CAMR1 = DF30FC-30DS: tolerance: 20.F0896.030
CLED1 = LED1608AKH20: tolerance: 83.19217.I70
CN1-CN16 = SUL-1315A1M: tolerance: 34.4VL24.001
CPU1 = BGA1380M17-UH41: tolerance: 071.CHERY.000U
D1701-D1708 D1710 D2901 D2902 = SOD923-10D6AKH16: tolerance: 83.1R003.Y8F
D1709 PD4604 = SOD323-2513AKH36: tolerance: 83.5R603.Z3F
D2101-D2103 D2106 D2107 D4501-D4503 = VARISTOR-402-H19: tolerance: 69.80028.021
D2201-D2205 D5417 D5418 = SOD882-10D6-1H20: tolerance: 83.05725.0A0
D2301-D2308 D5401-D5404 = SOD-523-4H28: tolerance: 75.05125.070
D2401-D2405 = D402H18: tolerance: 83.10402.0A0
D3001 D3403-D3405 D5412 PD4601 PD4605 PD4606 = SOD323AKH38: tolerance: 83.2R004.08F
D3401 D4402 D4403 = SC75-1D6-312H24: tolerance: 83.BA054.H81
D4001 D4002 D4401 PD4607 = SOD123AK-3719-UH40: tolerance: 83.3R004.F8H
D4101 = SOD882-10D6-1H20: tolerance: 83.0005V.CAF
D5405 D5411 = SOT-323H44: tolerance: 83.BAT54.B81
D5413-D5416 = D0201H13: tolerance: 83.00525.0A0
DB2 = FH34SRJ-6S-0D5SH-50-U: tolerance: 020.K0063.0006
ECDBG1 = 50521-01001-001: tolerance: 020.K0096.0010
ECOMP3 = LGA16-3030-H40: tolerance: 74.00303.BBZ
EMMC1 = BGA153G115130-1H40: tolerance: 072.KMCG8.0B0U
GYRO1 = LGA16-3030-H40: tolerance: 074.3GD20.00B0
H1 H5-H10 = HOLE197R79: tolerance: ZZ.00PAD.DU1
H3 H4 = HOLE197R103: tolerance: ZZ.00PAD.HA1
HALL1 = SOT23-2D8-123H52: tolerance: 74.05712.0BB
HKEY1 VDKEY1 VUKEY1 = SKRTLAE010-U: tolerance: 62.40009.G71
JUSBC1 = SKT-USB30-118098-U1: tolerance: 062.10009.0251
L3101 L3102 L3105 L3106 = LD65D85-4PH20: tolerance: 68.DLP0N.20B
L3103 L3104 = LD85D65-4P-1H20: tolerance: 68.DLP0N.20A
L3401-L3405 = LD65D85-4PH20: tolerance: 68.02002.061
L4401 = L2520-D620H48: tolerance: 68.1005A.10I
L5202 = L4442-D820H48: tolerance: 68.1R010.20T
LCD1 = FH35C-45S-0D3SHW-50-U: tolerance: 020.K0074.0045
LED1 = LED3020-3P-6H44: tolerance: 83.12222.C70
MIC1 = WM7211IMS-RV: tolerance: 082.40009.0011
MSD1 = 503398-0891: tolerance: 62.10051.I71
MSIM1 = SF56S006V4AR2000: tolerance: 062.10008.0031
NFC1 = 51548-01541-W01: tolerance: 20.K0729.015
NGFF1 = AS0BC56-R15BB-7H-U: tolerance: 062.10007.0451
PC4501 PC4502 PC4504 PC4601 PC4609 PC4612 PC4613 PC4620 PC4621 PC4624 PC4631 = C402H22: tolerance: 78.10422.5FL
PC4505 = C402H22: tolerance: 078.33034.01FS
PC4615 = C402H22: tolerance: 78.47322.2FL
PC4616 = C603H36: tolerance: 78.22523.5BL
PC4626 PC4627 = C402H22: tolerance: 78.10134.1FL
PC4714 PC4721 PC4814 PC4816 = C603H36: tolerance: 78.47510.5BL
PC5005 PR4907-PR4909 R408 = R402H16: tolerance: 64.20025.6DL
PD4801 = D1006-0304AKH16: tolerance: 083.CDZ62.0BAF
PD5101 = SOT23-2D4-312H48: tolerance: 75.00054.E7D
PG4601-PG4605 = GAP-CLOSE-PWR-3: tolerance: ZZ.CLOSE.001
PKEY1 = SKTDLDE010: tolerance: 062.40001.0431
PL4601 = L6965-1330-UH60: tolerance: 068.2R210.1161
PL4701 PL4801 = L2520-D620H48: tolerance: 68.1R050.10R
PL4702-PL4708 PL4802-PL4807 = L2016-D516H40: tolerance: 68.R4750.10H
PMIC1 = BGA224J6D2H25: tolerance: 074.02613.0C7Z
PQ4601 PQ4603 = SOT-363H44: tolerance: 84.2N702.A3F
PQ4901 Q1702 Q1703 = SOT23DGS2D4H45: tolerance: 84.02301.G31
PR4601 PR4602 = R0201H12: tolerance: 63.2203C.1IL
PR4603 = R805H24: tolerance: 63.10031.16L
PR4605 = R603H22: tolerance: 64.20R05.55L
PR4606 PR4610 = R402H16: tolerance: 64.10015.6DL
PR4608 PR4624 PR4630 PR5003 = R402H16: tolerance: 64.10035.6DL
PR4613 PR4615 = R603H22: tolerance: 63.82234.15L
PR4614 PR4627 PR4632 PR4635 R503 R652 R722 R723 R728 R748 R750 R805 R1731 R1737 R1757 R2211 R2908-R2911 R2916 R2917 R2921 R2922 R2925 R3020 R3405 R3905 R4302 R5217 R5603 R5705 = R402H16: tolerance: 63.R0034.1DL
PR4617 = R603H22: tolerance: 63.00000.00L
PR4618 = R3720H40: tolerance: 64.R0105.7FL
PR4619 PR4646 PR4912 PR4914 = R402H16: tolerance: 64.10025.6DL
PR4620 PR4621 PR4625 PR4628 PR4629 PR4634 PR4636 PR4637 PR4650 R1749 R3403 R4017 R4020 R5410 = R402H16: tolerance: 63.10434.1DL
PR4622 = R2512H32: tolerance: 64.R0105.97L
PR4623 = R402H16: tolerance: 64.12125.6DL
PR4626 = R402H16: tolerance: 64.49935.6DL
PR4631 = R402H16: tolerance: 64.18235.6DL
PR4633 = R402H16: tolerance: 64.66525.6DL
PR4640 PR4642 PR4643 PR4645 R507-R509 R707 R711 R713 R719 R731-R733 R753 R754 R758 R1324-R1327 R1424-R1427 R1702 R1705-R1707 R1709 R1710 R1716-R1718 R1720 R1722-R1729 R1733-R1735 R1742 R1744 R1763-R1765 R1767 R1770 R1775-R1789 R1804 R3026 R3807 R4005 R4018 R4101 R4106 R4209 R5401 R5409 WR3703 WR3705 WR3708 = R0201H12: tolerance: 63.1033C.1IL
PR4901 = R805H24: tolerance: 64.R0105.D6L
PR4902-PR4905 = R402H16: tolerance: 64.2R005.6DL
PR4906 = R1206H32: tolerance: 64.R0055.81L
PR4911 PR5117 R2501 R2918 R3407 R3408 R4104 = R402H16: tolerance: 63.10234.1DL
PR4913 PR5105 PR5107 PR5110-PR5112 PR5114 PR5115 R802 R806 R1601 R1602 R1721 R2001 R2005 R2014-R2017 R2022 R2024-R2027 R2204-R2206 R2514 R2515 R2919 R2920 R2923 R2924 R3019 R3101 R3146 R3902 R3904 R4102 R4105 R4201-R4205 R4207 R4208 R4301 R5601 R5602 R5704 R5706 R5707 WR3706 WR3707 = 0R0402-PAD: tolerance: ZZ.R0402.001
PR5001 PR5002 = R402H16: tolerance: 64.22015.6DL
PR5101 PR5106 R410-R412 R417 R418 R720 R734 R741 R5211 = R402H16: tolerance: 63.10334.1DL
PR5102-PR5104 = R402H16: tolerance: 64.24925.6DL
PR5108 R510 R1711 R1712 R1714 R1715 R1758 R1760 R4303 R4903 R5723 R5724 = R0201H12: tolerance: 63.1023C.1IL
PR5109 = R402H16: tolerance: 64.47025.6DL
PR5113 R1738 R1743 R1746 R1748 R3002 = R402H16: tolerance: 64.10045.6DL
PU4601 = QFN28-G2D7H32: tolerance: 074.24770.0B03
PU4602 Q4501 = PPAK-8P-2H45: tolerance: 84.00407.A37
PU4603 = PPAK-8P-G5324H44-COLAY: tolerance: ZZ.00215.037
PU4604 = PPAK-8P-2H45: tolerance: 84.07121.037
Q501 Q3001 = SOT-323H44: tolerance: 84.27002.G31
Q1701 = SOT-23-10H44: tolerance: 84.03904.L06
R301 R302 = R402H16: tolerance: 64.18205.6DL
R307 R308 = R0201H12: tolerance: 64.10025.GIL
R309-R312 R2018-R2020 R2104 R2203 R2207 R2208 R2301-R2306 R2401 R2403 R2502 R2503 R2505 R2506 R2508-R2513 R3125-R3131 R3165 R4103 R4107-R4110 R5214 WR3704 WR3710-WR3713 = 0R0201-PAD: tolerance: ZZ.R0201.001
R402 R406 R502 R648 = R402H16: tolerance: 64.40205.6DL
R403 R404 = R0201H12: tolerance: 64.15005.GIL
R421-R423 R511 R604 R703 R704 R714 R742 R1708 R1713 R1719 R1730 R1732 R1736 R1740 R1741 R1745 R1747 R1752 R1761 R1769 R2002 R2504 R3001 R3021 R3022 R3401 R3402 R3404 R4003 R4310 R4311 R4403 R5717 R5720 R5725 R5726 = R0201H12: tolerance: 63.1043C.1IL
R501 R644 R749 = R0201H12: tolerance: 64.10005.GIL
R504 = R0201H12: tolerance: 64.80R65.GIL
R514 = R402H16: tolerance: 64.71505.6DL
R603 = R0201H11: tolerance: 64.90R95.GIL
R624-R637 R645 R647 R666 R667 R705 R724 R729 R2201 R2202 = R0201H12: tolerance: 64.22015.GIL
R640 = R402H16: tolerance: 64.45R35.6DL
R643 = R402H16: tolerance: 64.11305.6DL
R715 = R402H16: tolerance: 64.24915.6DL
R716 = R0201H12: tolerance: 63.2043C.1IL
R721 R1701 = R0201H12: tolerance: 64.49R95.GIL
R730 = R0201H12: tolerance: 63.1063C.1IL
R735-R738 R740 R751 = R0201H12: tolerance: 64.51R05.GIL
R739 = R0201H12: tolerance: 63.2033C.1IL
R1305-R1308 R1405-R1408 = R0201H12: tolerance: 64.24005.GIL
R1309-R1318 R1409-R1418 = R0201H12: tolerance: 64.40R25.GIL
R1322 R1323 R1422 R1423 R4902 = R0201H12: tolerance: 63.3013C.1IL
R1502 = R805H24: tolerance: 63.R0031.16L
R1739 R2021 R2517 R2518 R3162 R3164 R3166 R3169 R3172 R3173 R4004 R4006-R4010 R4012-R4014 R4021 WC3706 WC3707 WC3709 WL3701 = R0201H12: tolerance: 63.R003C.1IL
R1750 R4501 = R402H16: tolerance: 63.20434.1DL
R1754 = R402H16: tolerance: 64.95305.6DL
R1759 = R402H16: tolerance: 63.82234.1DL
R1801 R1802 = 0R0201-PAD: tolerance: ZZ.R0201.001; signal model: 2pins
R1803 R1805 R2912-R2915 = R0201H12: tolerance: 63.3323C.1IL
R2012 R2013 = R402H16: tolerance: 64.22R05.6DL
R2023 = R402H16: tolerance: 63.20334.1DL
R2107 R2108 = 0R0603-PAD-1-U: tolerance: ZZ.00PAD.M21
R2209 R2210 = R402H16: tolerance: 63.33034.1DL
R2903 = R402H16: tolerance: 64.15025.6DL
R2905 = R402H16: tolerance: 64.93125.6DL
R3016 R3017 R3161 R3163 R3167 R3168 R3170 R3171 = R0201H12: tolerance: 63.4723C.1IL
R4401 = R402H16: tolerance: 64.63425.6DL
R4402 = R402H16: tolerance: 64.30025.6DL
R4404 R4405 = R402H16: tolerance: 63.20234.1DL
R4502-R4504 = R402H14: tolerance: 63.10134.1DL
R4801 = R603H22: tolerance: 63.R0033.15L
R5212 = R0201H12: tolerance: 64.25535.GIL
R5213 = R0201H12: tolerance: 64.30035.GIL
R5215 = R0201H12: tolerance: 64.10035.GIL
R5216 = R0201H12: tolerance: 64.10015.GIL
R5218 = R0201H11: tolerance: 64.91025.GIL
R5219 = R0201H12: tolerance: 64.28025.GIL
R5403-R5406 R5412 = R0201H12: tolerance: 63.1013C.1IL
R5712 = 0R0402-PAD: tolerance: ZZ.R0402.001; signal model: 2pins
R5721 = R402H16: tolerance: 64.29435.6DL
R5722 = R402H16: tolerance: 64.34035.L0L
